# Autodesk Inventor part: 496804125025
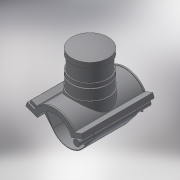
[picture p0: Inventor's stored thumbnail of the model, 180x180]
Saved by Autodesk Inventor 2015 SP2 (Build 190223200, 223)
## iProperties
Created: 2017-07
Part Number: 496804125025
Material: Generic
Description: PLASSON BALLOON SADDLE 125-2.1/2"
Document SubType Name: Modeling
Designer: KIM
Density: 1 g/cm^3
Appearance: Default
Author: KIM
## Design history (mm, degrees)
derived "496804.ipt"
feature "Solid1::496804.ipt"
feature "Solid2::496804.ipt"
tag "TaggingFeature1"
body "Solid1"
body "Solid2"
other parameters: "d0" = 125, "d1" = 143.75, "d4" = 176, "d5" = 0, "d40" = 74.75, "d96" = 146.625, "d97" = 3.52, "d98" = 0, "d120" = 140 deg, "d121" = 24.228, "d122" = 20 deg, "d123" = 287.5, "d124" = 86.25, "d126" = 0, "d143" = 128.75, "d145" = 14.42308, "d149" = 1.875, "d150" = 15.86538, "d153" = 176, "d154" = 0, "d159" = 3.75, "d161" = 1.875, "d162" = 105.6, "d163" = 0, "d164" = 62.5, "d168" = 75.65789, "d170" = 1.875, "d172" = 0, "d173" = 1, "d175" = 62.5, "d176" = 20 deg, "d177" = 15, "d180" = 0, "d185" = 57.2, "d186" = 57.2, "d187" = 71.875, "d188" = 5.625, "d190" = 0, "d191" = 115, "d193" = 3.75, "d194" = 4.4, "d195" = 90 deg, "d197" = 0, "d199" = 0, "d200" = 105, "d201" = 1, "d203" = 94.5, "d204" = 97.65, "d205" = 85.5, "d206" = 1.8, "d207" = 52.5, "d208" = 42, "d209" = 84, "d210" = 15.75, "d214" = 143.75, "d216" = 0, "d217" = 84.5, "d218" = 15, "d219" = 6.25, "d220" = 15.98, "d221" = 8 deg, "d223" = 14.52916, "d224" = 7.26458, "d226" = 0, "d227" = -17.6, "d228" = 1.875, "d229" = 27.5, "d_" = 125, "B_" = 169, "H_" = 105, "L_" = 176, "d_t" = 6, "d148" = 1.875, "d160" = 1.875, "d169" = 1.875, "d192" = 3.75, "d222" = 18.16145
